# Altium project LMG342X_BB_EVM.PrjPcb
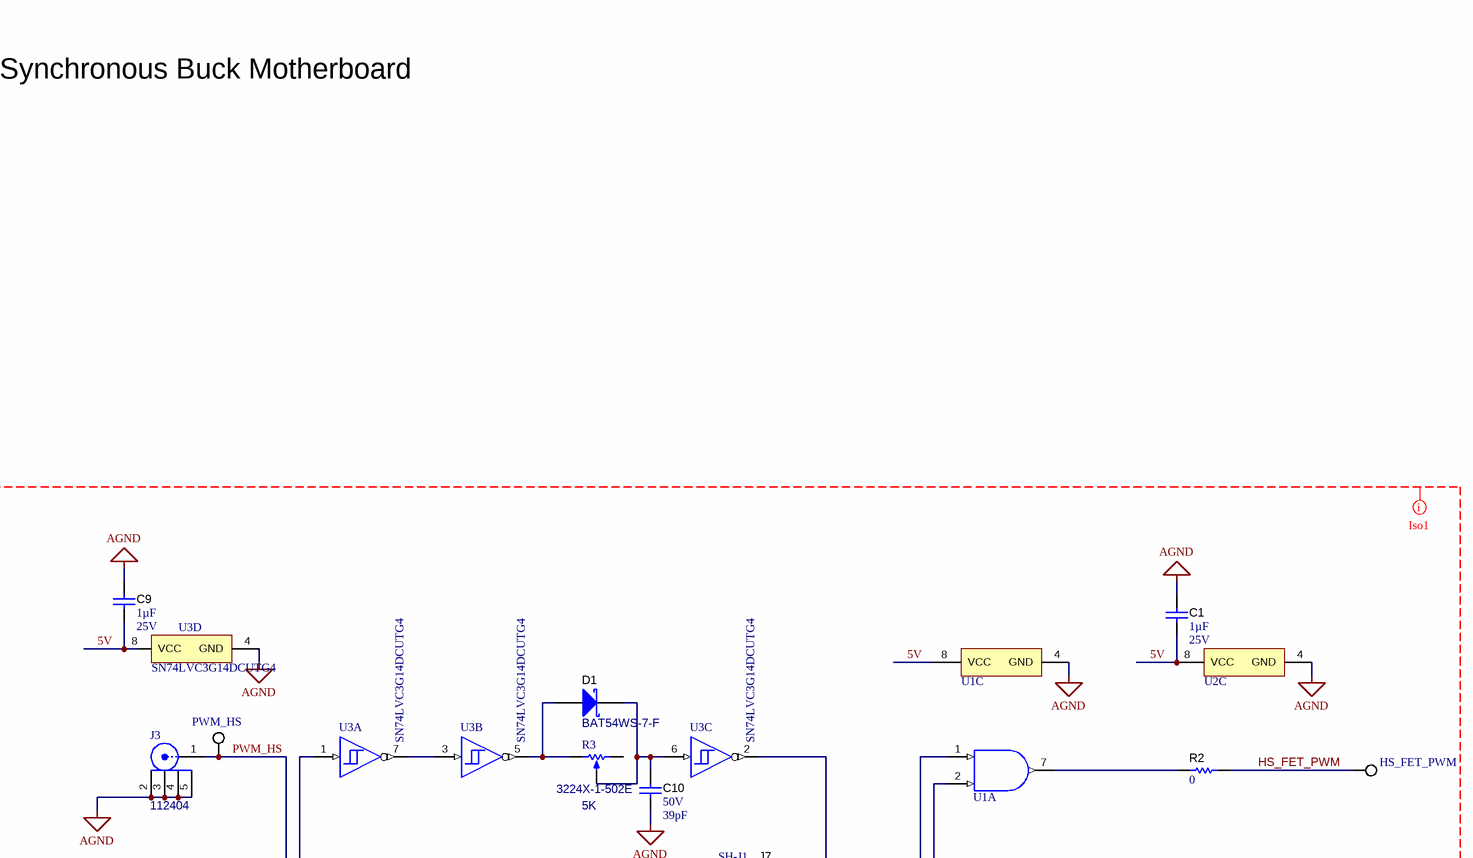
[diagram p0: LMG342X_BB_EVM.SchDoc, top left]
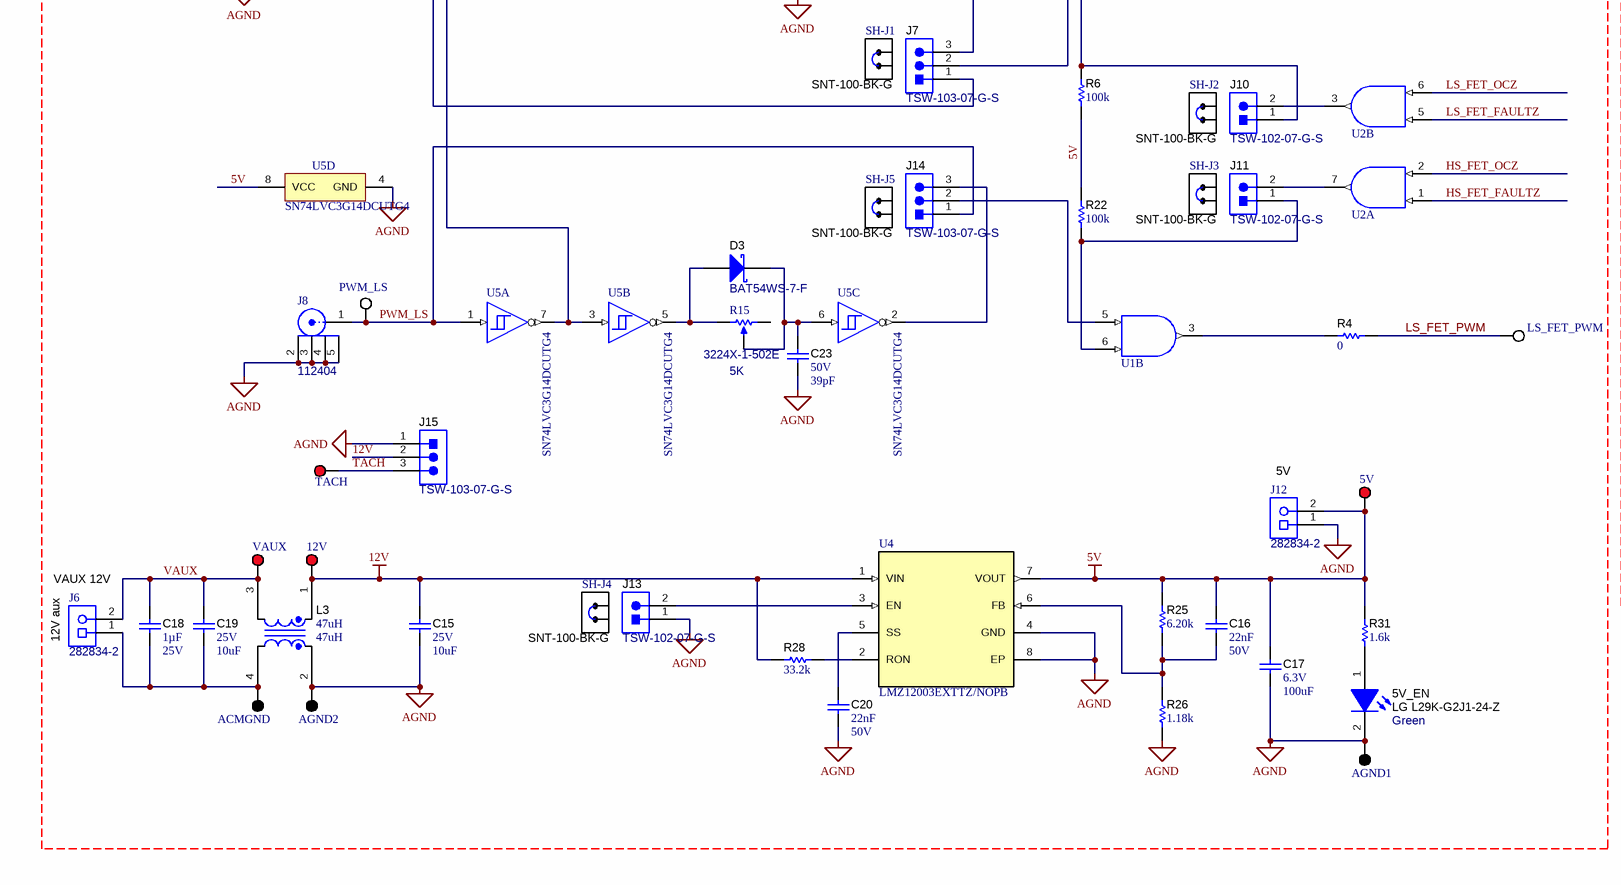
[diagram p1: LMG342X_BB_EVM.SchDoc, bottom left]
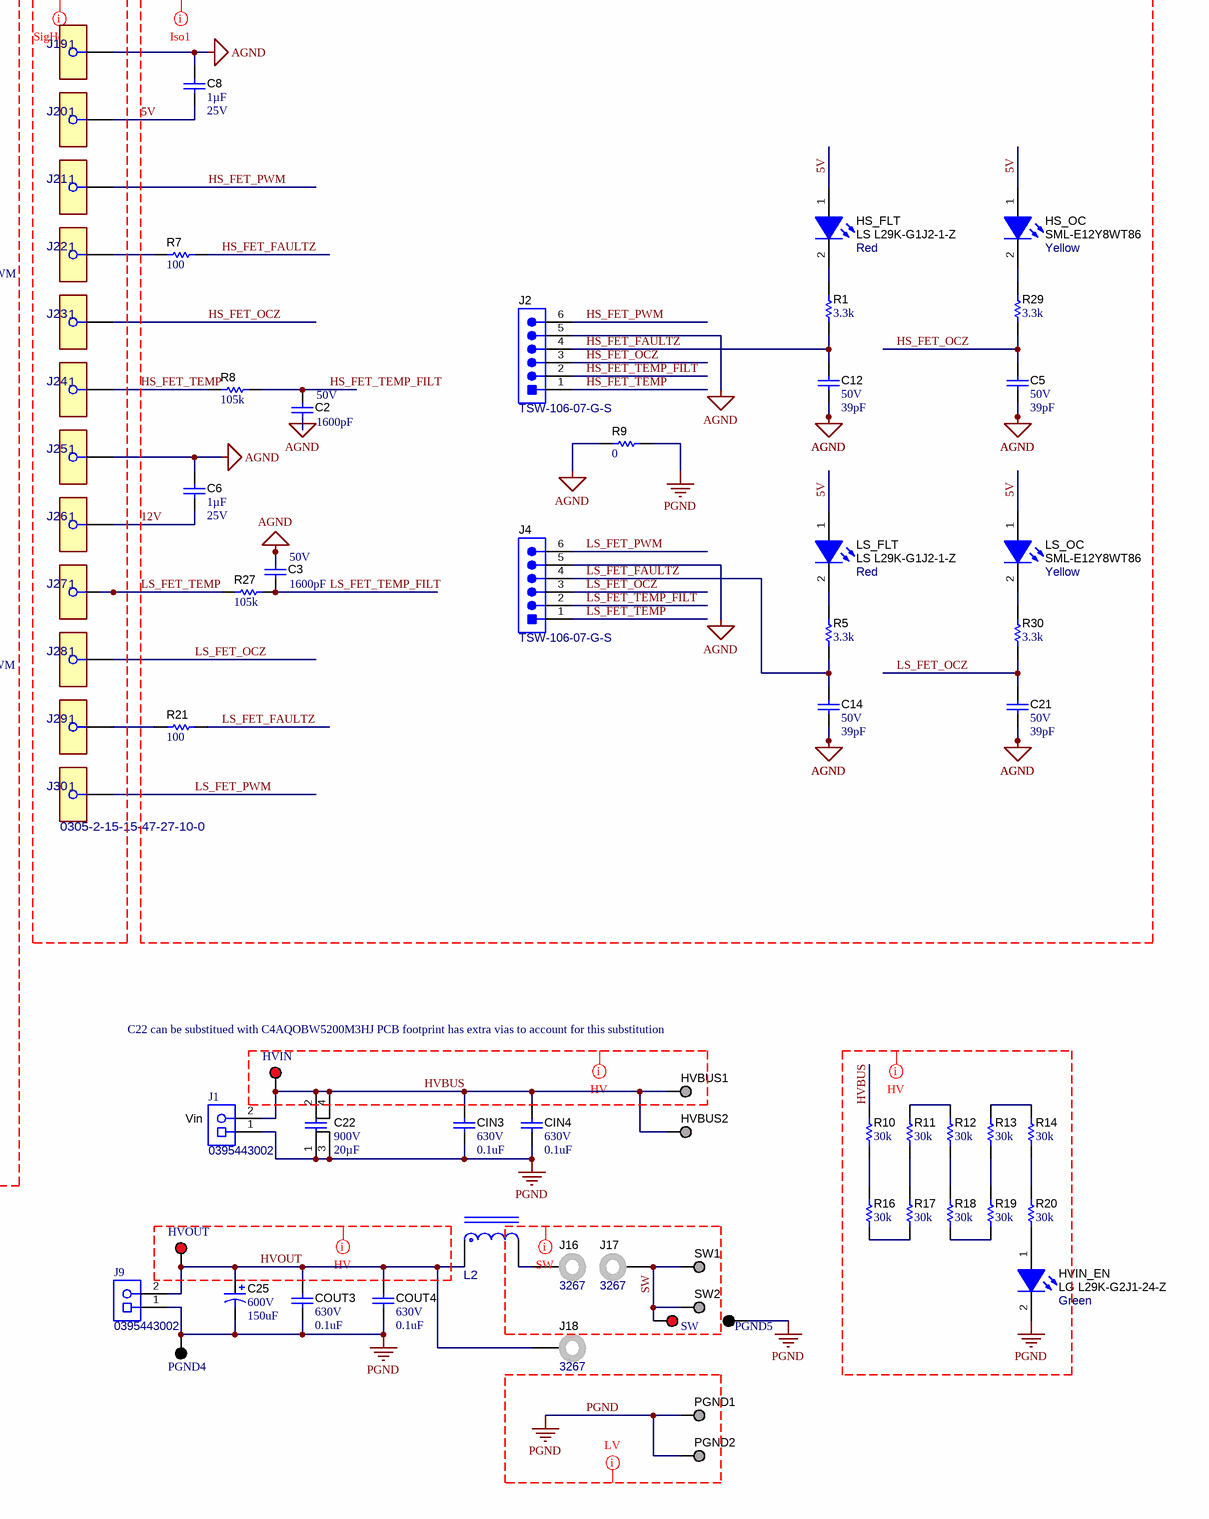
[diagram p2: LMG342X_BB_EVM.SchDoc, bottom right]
CopyrightYear: 2020; PCB_Layout: Kyle Wolf; PCB_Rev: A1; PRJ_Customer: General Release; PRJ_Engineer: Kyle Wolf; PRJ_Number: HVP049; PRJ_Title: LMG342X-BB-EVM; SCH_Rev: A1; TechSupport: http://www.ti.com/support; TID: N/A
2 sheets, 158 parts. Net scope: global (net labels, ports and power ports of the same name join across sheets).
Board file: LMG342X_BB_EVM.PcbDoc
Sheets:
  LMG342X_BB_EVM.SchDoc
  LMG342X_BB_EVM_Hardware.SchDoc

## Sheet LMG342X_BB_EVM.SchDoc
size 558 x 431 mm; Date: Not shown in title block; ApprovedBy: Not shown in title block; CheckedBy: Not shown in title block; Author: Not shown in title block; CompanyName: Not shown in title block; Engineer: Not shown in title block; Organization: Not shown in title block; Address1: Not shown in title block; Address2: Not shown in title block; Address3: Not shown in title block; Address4: Not shown in title block; DocumentNumber: 1; Revision: Use project parameter SCH_Rev; SheetNumber: 2; SheetTotal: 3; PageSetup: Record=PageOptions¦CenterHorizontal=True¦CenterVertical=True¦PrintScale=1.00¦XCorrection=1.00¦YCorrection=1.00¦PrintKind=0¦BorderSize=5000000¦LeftOffset=0¦BottomOffset=0¦Orientation=2¦PaperLength=1000¦PaperWidth=1000¦Scale=100¦PaperSource=15¦PrintQuality=600¦MediaType=1¦DitherType=10¦PaperKind=Letter¦PrintScaleMode=1

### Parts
5V  5005  [Keystone5005]  (value not drawn)
5V_EN  LG L29K-G2J1-24-Z  value Green  [LG L29K_GREEN]
12V  5005  [Keystone5005]  (value not drawn)
ACMGND  5006  [Keystone5006]  (value not drawn)
AGND1  5006  [Keystone5006]  (value not drawn)
AGND2  5006  [Keystone5006]  (value not drawn)
C1  Cap_F: 1µF  VDC_V: 25V  [0603]  (hidden comment: CGA3E1X7R1E105K080AD)
C2  VDC_V: 50V  ValueDisplayed: 1600pF  [0603]  (hidden comment: GRM1885C1H162JA01D)
C3  VDC_V: 50V  ValueDisplayed: 1600pF  [0603]  (hidden comment: GRM1885C1H162JA01D)
C5  VDC_V: 50V  ValueDisplayed: 39pF  [0603]  (hidden comment: GRM1885C1H390JA01D)
C6  Cap_F: 1µF  VDC_V: 25V  [0603]  (hidden comment: CGA3E1X7R1E105K080AD)
C8  Cap_F: 1µF  VDC_V: 25V  [0603]  (hidden comment: CGA3E1X7R1E105K080AD)
C9  Cap_F: 1µF  VDC_V: 25V  [0603]  (hidden comment: CGA3E1X7R1E105K080AD)
C10  VDC_V: 50V  ValueDisplayed: 39pF  [0603]  (hidden comment: GRM1885C1H390JA01D)
C12  VDC_V: 50V  ValueDisplayed: 39pF  [0603]  (hidden comment: GRM1885C1H390JA01D)
C14  VDC_V: 50V  ValueDisplayed: 39pF  [0603]  (hidden comment: GRM1885C1H390JA01D)
C15  VDC_V: 25V  ValueDisplayed: 10uF  [0603]  (hidden comment: GRT188R61E106ME13D)
C16  Cap_F: 22nF  VDC_V: 50V  [0603]  (hidden comment: 885012206091)
C17  VDC_V: 6.3V  ValueDisplayed: 100uF  [0805_HV]  (hidden comment: GRM21BR60J107M)
C18  Cap_F: 1µF  VDC_V: 25V  [0603]  (hidden comment: CGA3E1X7R1E105K080AD)
C19  VDC_V: 25V  ValueDisplayed: 10uF  [0805_HV]  (hidden comment: CL21A106KAFN3NE)
C20  Cap_F: 22nF  VDC_V: 50V  [0603]  (hidden comment: 885012206091)
C21  VDC_V: 50V  ValueDisplayed: 39pF  [0603]  (hidden comment: GRM1885C1H390JA01D)
C22  VDC_V: 900V  ValueDisplayed: 20µF  [FE37M]  (hidden comment: FE37M6C0206KB)
C23  VDC_V: 50V  ValueDisplayed: 39pF  [0603]  (hidden comment: GRM1885C1H390JA01D)
C25  VDC_V: 600V  ValueDisplayed: 150uF  [Nichicon_3000x5000_Snap]  (hidden comment: LGN2X151MELB50)
CIN3  VDC_V: 630V  ValueDisplayed: 0.1uF  [1812_HV]  (hidden comment: GRM43DR72J104KW01L)
CIN4  VDC_V: 630V  ValueDisplayed: 0.1uF  [1812]  (hidden comment: GRM43DR72J104KW01L)
COUT3  VDC_V: 630V  ValueDisplayed: 0.1uF  [1812_HV]  (hidden comment: GRM43DR72J104KW01L)
COUT4  VDC_V: 630V  ValueDisplayed: 0.1uF  [1812_HV]  (hidden comment: GRM43DR72J104KW01L)
D1  BAT54WS-7-F  [SOD-323]
D3  BAT54WS-7-F  [SOD-323]
HS_FET_PWM  5007  [Keystone5007]  (value not drawn)
HS_FLT  LS L29K-G1J2-1-Z  value Red  [LS L29K_Red]
HS_OC  SML-E12Y8WT86  value Yellow  [SML-E1_Yellow]
HVBUS1  0312-0-15-15-34-27-10-0  [Mill-Max_0312-0-15-15-34-27-10-0]  (value not drawn)
HVBUS2  0312-0-15-15-34-27-10-0  [Mill-Max_0312-0-15-15-34-27-10-0]  (value not drawn)
HVIN  5005  [Keystone5005]  (value not drawn)
HVIN_EN  LG L29K-G2J1-24-Z  value Green  [LG L29K_GREEN]
HVOUT  5005  [Keystone5005]  (value not drawn)
J1  0395443002  [Molex_0395443002]
J2  TSW-106-07-G-S  [TSW-106-07-G-S]
J3  112404  [Amphenol_112404]
J4  TSW-106-07-G-S  [TSW-106-07-G-S]
J6  282834-2  [TEC_282834-2]
J7  TSW-103-07-G-S  [TSW-103-07-G-S]
J8  112404  [Amphenol_112404]
J9  0395443002  [Molex_0395443002]
J10  TSW-102-07-G-S  [TSW-102-07-G-S]
J11  TSW-102-07-G-S  [TSW-102-07-G-S]
J12  282834-2  [TEC_282834-2]
J13  TSW-102-07-G-S  [TSW-102-07-G-S]
J14  TSW-103-07-G-S  [TSW-103-07-G-S]
J15  TSW-103-07-G-S  [TSW-103-07-G-S]
J16  3267  [Pomona_3267]
J17  3267  [Pomona_3267]
J18  3267  [Pomona_3267]
J19  0305-2-15-15-47-27-10-0  [FP-0305-2-15-15-47-27-10-0_CONN_PIN_RCPT-MFG]  (value not drawn)
J20  0305-2-15-15-47-27-10-0  [FP-0305-2-15-15-47-27-10-0_CONN_PIN_RCPT-MFG]  (value not drawn)
J21  0305-2-15-15-47-27-10-0  [FP-0305-2-15-15-47-27-10-0_CONN_PIN_RCPT-MFG]  (value not drawn)
J22  0305-2-15-15-47-27-10-0  [FP-0305-2-15-15-47-27-10-0_CONN_PIN_RCPT-MFG]  (value not drawn)
J23  0305-2-15-15-47-27-10-0  [FP-0305-2-15-15-47-27-10-0_CONN_PIN_RCPT-MFG]  (value not drawn)
J24  0305-2-15-15-47-27-10-0  [FP-0305-2-15-15-47-27-10-0_CONN_PIN_RCPT-MFG]  (value not drawn)
J25  0305-2-15-15-47-27-10-0  [FP-0305-2-15-15-47-27-10-0_CONN_PIN_RCPT-MFG]  (value not drawn)
J26  0305-2-15-15-47-27-10-0  [FP-0305-2-15-15-47-27-10-0_CONN_PIN_RCPT-MFG]  (value not drawn)
J27  0305-2-15-15-47-27-10-0  [FP-0305-2-15-15-47-27-10-0_CONN_PIN_RCPT-MFG]  (value not drawn)
J28  0305-2-15-15-47-27-10-0  [FP-0305-2-15-15-47-27-10-0_CONN_PIN_RCPT-MFG]  (value not drawn)
J29  0305-2-15-15-47-27-10-0  [FP-0305-2-15-15-47-27-10-0_CONN_PIN_RCPT-MFG]  (value not drawn)
J30  0305-2-15-15-47-27-10-0  [FP-0305-2-15-15-47-27-10-0_CONN_PIN_RCPT-MFG]
L2  750317345  [FP-750317345_PTH_D53MM34-MFG]  (value not drawn)
L3  value 47uH  [DRQ73]  (hidden comment: DRQ73-470-R)
LS_FET_PWM  5007  [Keystone5007]  (value not drawn)
LS_FLT  LS L29K-G1J2-1-Z  value Red  [LS L29K_Red]
LS_OC  SML-E12Y8WT86  value Yellow  [SML-E1_Yellow]
PGND1  0312-0-15-15-34-27-10-0  [Mill-Max_0312-0-15-15-34-27-10-0]  (value not drawn)
PGND2  0312-0-15-15-34-27-10-0  [Mill-Max_0312-0-15-15-34-27-10-0]  (value not drawn)
PGND4  5006  [Keystone5006]  (value not drawn)
PGND5  5006  [Keystone5006]  (value not drawn)
PWM_HS  5007  [Keystone5007]  (value not drawn)
PWM_LS  5007  [Keystone5007]  (value not drawn)
R1  ValueDisplayed: 3.3k  [0603]  (hidden comment: CRCW06033K30JNEA)
R2  ValueDisplayed: 0  [0603_HV]  (hidden comment: CRCW06030000Z0EA)
R3  3224X-1-502E  value 5K  [TRIM_3224X]
R4  ValueDisplayed: 0  [0603_HV]  (hidden comment: CRCW06030000Z0EA)
R5  ValueDisplayed: 3.3k  [0603]  (hidden comment: CRCW06033K30JNEA)
R6  ValueDisplayed: 100k  [0603]  (hidden comment: CRCW0603100KJNEAC)
R7  ValueDisplayed: 100  [0603]  (hidden comment: CRCW0603100RJNEA)
R8  ValueDisplayed: 105k  [0603]  (hidden comment: RC0603FR-07105KL)
R9  ValueDisplayed: 0  [0603_HV]  (hidden comment: CRCW06030000Z0EA)
R10  ValueDisplayed: 30k  [1206]  (hidden comment: CRCW120630K0JNEA)
R11  ValueDisplayed: 30k  [1206]  (hidden comment: CRCW120630K0JNEA)
R12  ValueDisplayed: 30k  [1206]  (hidden comment: CRCW120630K0JNEA)
R13  ValueDisplayed: 30k  [1206]  (hidden comment: CRCW120630K0JNEA)
R14  ValueDisplayed: 30k  [1206]  (hidden comment: CRCW120630K0JNEA)
R15  3224X-1-502E  value 5K  [TRIM_3224X]
R16  ValueDisplayed: 30k  [1206]  (hidden comment: CRCW120630K0JNEA)
R17  ValueDisplayed: 30k  [1206]  (hidden comment: CRCW120630K0JNEA)
R18  ValueDisplayed: 30k  [1206]  (hidden comment: CRCW120630K0JNEA)
R19  ValueDisplayed: 30k  [1206]  (hidden comment: CRCW120630K0JNEA)
R20  ValueDisplayed: 30k  [1206]  (hidden comment: CRCW120630K0JNEA)
R21  ValueDisplayed: 100  [0603]  (hidden comment: CRCW0603100RJNEA)
R22  ValueDisplayed: 100k  [0603]  (hidden comment: CRCW0603100KJNEAC)
R25  ValueDisplayed: 6.20k  [0603]  (hidden comment: RC0603FR-076K2L)
R26  ValueDisplayed: 1.18k  [0603]  (hidden comment: RC0603FR-071K18L)
R27  ValueDisplayed: 105k  [0603]  (hidden comment: RC0603FR-07105KL)
R28  ValueDisplayed: 33.2k  [0603]  (hidden comment: RT0603BRD0733K2L)
R29  ValueDisplayed: 3.3k  [0603]  (hidden comment: CRCW06033K30JNEA)
R30  ValueDisplayed: 3.3k  [0603]  (hidden comment: CRCW06033K30JNEA)
R31  ValueDisplayed: 1.6k  [0603]  (hidden comment: CRCW06031K60JNEA)
SH-J1  SNT-100-BK-G  [SNT-100-BK-G]
SH-J2  SNT-100-BK-G  [SNT-100-BK-G]
SH-J3  SNT-100-BK-G  [SNT-100-BK-G]
SH-J4  SNT-100-BK-G  [SNT-100-BK-G]
SH-J5  SNT-100-BK-G  [SNT-100-BK-G]
SW  5005  [Keystone5005]  (value not drawn)
SW1  0312-0-15-15-34-27-10-0  [Mill-Max_0312-0-15-15-34-27-10-0]  (value not drawn)
SW2  0312-0-15-15-34-27-10-0  [Mill-Max_0312-0-15-15-34-27-10-0]  (value not drawn)
TACH  5005  [Keystone5005]  (value not drawn)
U1  SN74LVC2G08IDCTRQ1  [DCT0008A_N]  (value not drawn)  (parts A,B,C of 3)
U2  SN74LVC2G08IDCTRQ1  [DCT0008A_N]  (value not drawn)  (parts A,B,C of 3)
U3  SN74LVC3G14DCUTG4  [DCU0008A_N]  (parts A,B,C,D of 4)
U4  LMZ12003EXTTZ/NOPB  [NDW0007A_V]
U5  SN74LVC3G14DCUTG4  [DCU0008A_N]  (parts A,B,C,D of 4)
VAUX  5005  [Keystone5005]  (value not drawn)

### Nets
5V: 5V.1 C1.2 C8.1 C9.2 C16.1 C17.1 HS_FLT.1(A) HS_OC.1(A) J12.2 J20.1 LS_FLT.1(A) LS_OC.1(A) R6.1 R22.2 R25.2 R31.2 U1.8(VCC) U2.8(VCC) U3.8(VCC) U4.7(VOUT) U5.8(VCC)
12V: 12V.1 C6.1 C15.1 J15.2 J26.1 L3.1 R28.1 U4.1(VIN)
AGND: 5V_EN.2(K) AGND1.1 AGND2.1 C1.1 C2.1 C3.1 C5.2 C6.2 C8.2 C9.1 C10.2 C12.2 C14.2 C15.2 C17.2 C20.2 C21.2 C23.2 J2.5 J3.2 J3.3 J3.4 J3.5 J4.5 J8.2 J8.3 J8.4 J8.5 J12.1 J13.1 J15.1 J19.1 J25.1 L3.2 R9.1 R26.1 U1.4(GND) U2.4(GND) U3.4(GND) U4.4(GND) U4.8(EP) U5.4(GND)
PGND: C22.1 C22.3 C25.2(-) CIN3.2 CIN4.2 COUT3.2 COUT4.2 HVIN_EN.2(K) J1.1 J9.1 PGND1.1 PGND2.1 PGND4.1 PGND5.1 R9.2
HS_FET_FAULTZ: C12.1 J2.4 R1.1 R7.2 U2.1(1A)
HS_FET_OCZ: C5.1 J2.3 J23.1 R29.1 U2.2(1B)
HS_FET_PWM: HS_FET_PWM.1 J2.6 J21.1 R2.2
HS_FET_TEMP: J2.1 J24.1 R8.1
HS_FET_TEMP_FILT: C2.2 J2.2 R8.2
HVBUS: C22.2 C22.4 CIN3.1 CIN4.1 HVBUS1.1 HVBUS2.1 HVIN.1 J1.2 R10.2
HVOUT: C25.1(+) COUT3.1 COUT4.1 HVOUT.1 J9.2 J18.1 L2.1(S)
LS_FET_FAULTZ: C14.1 J4.4 R5.1 R21.2 U2.5(2A)
LS_FET_OCZ: C21.1 J4.3 J28.1 R30.1 U2.6(2B)
LS_FET_PWM: J4.6 J30.1 LS_FET_PWM.1 R4.2
LS_FET_TEMP: J4.1 J27.1 R27.1
LS_FET_TEMP_FILT: C3.2 J4.2 R27.2
PWM_HS: J3.1 J7.1 PWM_HS.1
PWM_LS: J8.1 J14.1 PWM_LS.1 U5.1(1A)
SW: J17.1 SW.1 SW1.1 SW2.1
TACH: J15.3 TACH.1
VAUX: C18.1 C19.1 J6.2 L3.3 VAUX.1
Net5V_EN_1: 5V_EN.1(A) R31.1
NetACMGND_1: ACMGND.1 C18.2 C19.2 J6.1 L3.4
NetC10_1: C10.1 D1.1(K) R3.2(WIPER) U3.6(3A)
NetC16_2: C16.2 R25.1 R26.2 U4.6(FB)
NetC20_1: C20.1 U4.5(SS)
NetC23_1: C23.1 D3.1(K) R15.2(WIPER) U5.6(3A)
NetD1_2: D1.2(A) R3.1(CCW) U3.5(2Y)
NetD3_2: D3.2(A) R15.1(CCW) U5.5(2Y)
NetHS_FLT_2: HS_FLT.2(K) R1.2
NetHS_OC_2: HS_OC.2(K) R29.2
NetHVIN_EN_1: HVIN_EN.1(A) R20.1
NetJ7_2: J7.2 U1.1(1A)
NetJ7_3: J7.3 U3.2(3Y)
NetJ10_1: J10.1 R6.2 U1.2(1B)
NetJ10_2: J10.2 U2.3(2Y)
NetJ11_1: J11.1 R22.1 U1.6(2B)
NetJ11_2: J11.2 U2.7(1Y)
NetJ13_2: J13.2 U4.3(EN)
NetJ14_2: J14.2 U1.5(2A)
NetJ14_3: J14.3 U5.2(3Y)
NetJ16_1: J16.1 L2.2(F)
NetJ22_1: J22.1 R7.1
NetJ29_1: J29.1 R21.1
NetLS_FLT_2: LS_FLT.2(K) R5.2
NetLS_OC_2: LS_OC.2(K) R30.2
NetR2_1: R2.1 U1.7(1Y)
NetR4_1: R4.1 U1.3(2Y)
NetR10_1: R10.1 R16.2
NetR11_1: R11.1 R17.2
NetR11_2: R11.2 R12.2
NetR12_1: R12.1 R18.2
NetR13_1: R13.1 R19.2
NetR13_2: R13.2 R14.2
NetR14_1: R14.1 R20.2
NetR16_1: R16.1 R17.1
NetR18_1: R18.1 R19.1
NetR28_2: R28.2 U4.2(RON)
NetU3_1: U3.1(1A) U5.3(2A) U5.7(1Y)
NetU3_3: U3.3(2A) U3.7(1Y)

Not connected (* = marked no-connect by the designer): R3 3(CW); R15 3(CW)

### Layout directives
net class HV: HVBUS, HVOUT, PGND
net class SW: SW
net class LV: PGND
net class Iso1: 5V, 12V, AGND, HS_FET_FAULTZ, HS_FET_OCZ, HS_FET_PWM, HS_FET_TEMP, HS_FET_TEMP_FILT, LS_FET_FAULTZ, LS_FET_OCZ, LS_FET_PWM, LS_FET_TEMP, LS_FET_TEMP_FILT, PGND, PWM_HS, PWM_LS, TACH, VAUX
net class SigHeader: (no net found under the mark)

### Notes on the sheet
- TI HV Synchronous Buck Motherboard
- (near J12) 5V
- (near J6) 12V aux
- (near J6) VAUX 12V
- C22 can be substitued with C4AQOBW5200M3HJ PCB footprint has extra vias to account for this substitution
- (near J1) Vin

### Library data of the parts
5V 12V HVIN HVOUT SW TACH VAUX = CMP-0055142-1: Test Point, Compact, Red, TH; Manufacturer: Keystone; CNHeader: FALSE; Green_Lifecycle: Active; Green_REACh: Passed; ContactFinish: Silver; CT: TRUE
5V_EN HVIN_EN = CMP-0002874-2: LED, Green, SMD; Manufacturer: OSRAM; Io_A: 2mA; Value2: 1.7V; Value1: W; Tjmax_C: 110°C
ACMGND AGND1 AGND2 PGND4 PGND5 = CMP-0055143-1: Test Point, Compact, Black, TH; Manufacturer: Keystone; CNHeader: FALSE; Green_Lifecycle: Active; Green_REACh: Passed; ContactFinish: Silver; CT: TRUE
C1 C6 C8 C9 C18 = CMP-0082523-1: CAP, CERM, 1 µF, 25 V,+/- 10%, X7R, AEC-Q200 Grade 1, 0603; Manufacturer: TDK; SizeAreaWB_mm2: 4.68; SizeArea_mm2: 1.28; AEC Qualified: Y; AEC Category: Q200; Value: 1uF; TaMax_C: 125°C; SizeZ_mm: 1; Polarized: N; TaMin_C: -55°C; SizeY_mm: 0.8; U/M: EA; SizeX_mm: 1.6
C2 C3 = CMP-0007189-1: CAP, CERM, 1600 pF, 50 V, +/- 5%, C0G/NP0, 0603; Manufacturer: MuRata; TaMin_C: -55°C; Polarized: N; SizeAreaWB_mm2: 4.68; Value1: Unknown; U/M: EA; Value: 1600pF; TaMax_C: 125°C; SizeZ_mm: 1; SizeX_mm: 1.6; SizeY_mm: 0.8; SizeArea_mm2: 1.28; Cap_F: 1.6nF; AEC Category: Q200
C5 C10 C12 C14 C21 C23 = CMP-0007214-4: CAP, CERM, 39 pF, 50 V, +/- 5%, C0G/NP0, 0603; Manufacturer: MuRata; TaMin_C: -55°C; Polarized: N; SizeAreaWB_mm2: 4.68; Value1: Unknown; U/M: EA; Value: 39pF; TaMax_C: 125°C; SizeZ_mm: 1; SizeX_mm: 1.6; SizeY_mm: 0.8; SizeArea_mm2: 1.28; AEC Category: Q200
C15 = CMP-0007501-1: CAP, CERM, 10 uF, 25 V, +/- 20%, X5R, 0603; Manufacturer: MuRata; TaMin_C: -55°C; Polarized: N; SizeAreaWB_mm2: 4.68; Value1: Unknown; U/M: EA; Value: 10uF; TaMax_C: 85°C; SizeZ_mm: 1; SizeX_mm: 1.6; SizeY_mm: 0.8; SizeArea_mm2: 1.28; Cap_F: 10µF; AEC Category: Q200
C16 C20 = CMP-0006836-1: CAP, CERM, 0.022 uF, 50 V, +/- 10%, X7R, 0603; Manufacturer: Wurth Elektronik; TaMin_C: -55°C; Polarized: N; SizeAreaWB_mm2: 4.68; Value1: Unknown; U/M: EA; TaMax_C: 125°C; SizeZ_mm: 1; SizeX_mm: 1.6; SizeY_mm: 0.8; SizeArea_mm2: 1.28; AEC Category: Q200
C17 = CMP-0008280-1: CAP, CERM, 100 uF, 6.3 V, +/- 20%, X5R, 0805; Manufacturer: MuRata; TaMin_C: -55°C; Polarized: N; SizeAreaWB_mm2: 6.75; Value1: Unknown; U/M: EA; Value: 100uF; TaMax_C: 85°C; SizeZ_mm: 1.45; SizeX_mm: 2; SizeY_mm: 1.25; Cap_Case: 0805; SizeArea_mm2: 2.5; Cap_F: 100µF; AEC Category: Q200
C19 = CMP-0007987-2: CAP, CERM, 10 uF, 25 V, +/- 10%, X5R, 0805; Manufacturer: Samsung Electro-Mechanics; TaMin_C: -55°C; Polarized: N; SizeAreaWB_mm2: 6.75; Value1: Unknown; U/M: EA; Value: 10uF; TaMax_C: 85°C; SizeZ_mm: 1.45; SizeX_mm: 2; SizeY_mm: 1.25; Cap_Case: 0805; SizeArea_mm2: 2.5; Cap_F: 10µF; AEC Category: Q200
C22 = CMP-0083986-1: CAP, Film, 20 µF, 900 V,+/- 10%, 0.0055 ohm, TH; Manufacturer: AVX; IRMS_A: 15A; SizeAreaWB_mm2: 1424; SizeArea_mm2: 1275; AEC Qualified: N; AEC Category: Q200; Value: 20uF; TaMax_C: 100°C; SizeZ_mm: 45.5; TaMin_C: -40°C; SizeY_mm: 30; CompType: Capacitor; SizeX_mm: 42.5; ESR_ohm: 5.5m; Cap_Case: 42.5x30x45mm
C25 = CMP-0010059-2: CAP, AL, 150 uF, 600 V, +/- 20%, TH; Manufacturer: Nichicon; TaMin_C: -25°C; Polarized: Y; SizeAreaWB_mm2: 1024; Value1: Unknown; U/M: EA; Value: 150uF; TaMax_C: 105°C; SizeZ_mm: 52; SizeX_mm: 30; Cap_Case: 30x50mm; SizeArea_mm2: 900; CompType: Capacitor; AEC Qualified: N; Cap_F: 150µF; IRMS_A: 830mA; AEC Category: Q200
CIN3 COUT3 COUT4 = CMP-0009455-2: CAP, CERM, 0.1 uF, 630 V, +/- 10%, X7R, 1812; Manufacturer: MuRata; TaMin_C: -55°C; Polarized: N; SizeAreaWB_mm2: 23.1; Value1: Unknown; U/M: EA; Value: 0.1uF; TaMax_C: 125°C; SizeZ_mm: 1.35; SizeX_mm: 4.5; SizeY_mm: 3.2; Cap_Case: 1812; SizeArea_mm2: 14.4; Cap_F: 100nF; AEC Category: Q200
CIN4 = CMP-0009455-2: CAP, CERM, 0.1 uF, 630 V, +/- 10%, X7R, 1812; Manufacturer: MuRata; TaMin_C: -55°C; Polarized: N; SizeAreaWB_mm2: 23.1; Value1: Unknown; U/M: EA; Value: 0.1uF; TaMax_C: 125°C; SizeZ_mm: 1.35; SizeX_mm: 4.5; SizeY_mm: 3.2; SizeArea_mm2: 14.4; Cap_F: 100nF; AEC Category: Q200
D1 D3 = CMP-0028458-1: Diode, Schottky, 30 V, 0.2 A, SOD-323; Manufacturer: Diodes Inc.; Io_A: 200mA; Green_Lifecycle: Active; SizeAreaWB_mm2: 8.695; Vr_V: 30V; Green_REACh: Passed; Value1: 0.2A; TJmax_C: 125°C; U/M: EA; Value: 30V; SizeZ_mm: 1; SizeX_mm: 2.7; SizeY_mm: 1.35; Vf_V: 700mV; Value2: 0.7V; SizeArea_mm2: 3.645; AEC Category: Q101
HS_FET_PWM LS_FET_PWM PWM_HS PWM_LS = CMP-0055144-1: Test Point, Compact, White, TH; Manufacturer: Keystone; CNHeader: FALSE; Green_Lifecycle: Active; Green_REACh: Passed; ContactFinish: Silver; CT: TRUE
HS_FLT LS_FLT = CMP-0002902-2: LED, Red, SMD; Manufacturer: OSRAM; Io_A: 20mA; Vr_V: 12V; Tjmax_C: 110°C; Value1: W; Angle: 160; Vf_V: 1.8V
HS_OC LS_OC = CMP-0002977-1: LED, Yellow, SMD; Manufacturer: Rohm; Io_A: 20mA; Power_TotalModule: 54mW; Vr_V: 5V; Tjmax_C: 85°C; Value1: 0.054W; U/M: EA; Ir_A: 10µA; Vf_V: 2.2V; LuminousIntensity_IV: 63
HVBUS1 HVBUS2 PGND1 PGND2 SW1 SW2 = CMP-0055026-1: Manufacturer: Mill-Max; CNHeader: FALSE; Green_Lifecycle: Active; Gender: Female; Green_REACh: Passed; CompType: Pin Receptacle; ContactFinish: Gold
J1 J9 = CMP-0055342-2: Terminal Block, 5.08mm, 2x1, TH; Manufacturer: Molex; Current_A: 15A; Green_Lifecycle: Not Set; Gender: Female; Green_REACh: Incomplete; Voltage_V: 300V; Row_Count: 1; Pitch_mm: 5.08
J2 J4 = CMP-0075413-2: Header, 100mil, 6x1, Gold, TH; Manufacturer: Samtec; Pitch_mm: 2.54; Cert_VDE: N; Gender: Male; Cert_CSA: Y; Voltage_V: 550V; Green_REACh: Passed; Current_A: 6.3A; Green_Lifecycle: Active; Row_Count: 1
J3 J8 = CMP-0055424-1: Connector, TH, BNC; Manufacturer: Amphenol Connex; CT: TRUE; Green_REACh: Incomplete; CNHeader: FALSE; Green_Lifecycle: Not Set
J6 J12 = CMP-0054974-1: Terminal Block, 2x1, 2.54mm, TH; Manufacturer: TE Connectivity; CNHeader: FALSE; Green_Lifecycle: Active; Green_REACh: Passed; CT: TRUE
J7 J14 J15 = CMP-0075407-2: Header, 100mil, 3x1, Gold, TH; Manufacturer: Samtec; Pitch_mm: 2.54; Cert_VDE: N; Gender: Male; Cert_CSA: Y; Voltage_V: 550V; Green_REACh: Passed; Current_A: 6.3A; Green_Lifecycle: Active; Row_Count: 1
J10 J11 J13 = CMP-0075405-2: Header, 100mil, 2x1, Gold, TH; Manufacturer: Samtec; Pitch_mm: 2.54; Cert_VDE: N; Gender: Male; Cert_CSA: Y; Voltage_V: 550V; Green_REACh: Passed; Current_A: 6.3A; Green_Lifecycle: Active; Row_Count: 1
J16-J18 = CMP-0055388-2: Standard Banana Jack, Uninsulated; Manufacturer: Pomona Electronics; CT: TRUE; Green_REACh: Incomplete; CNHeader: FALSE; Green_Lifecycle: Not Set
J19-J30 = CMP-0120348-1: Pin Receptacle Connector 0.025" ~ 0.037" (0.64mm ~ 0.94mm) No Tail Solder; Manufacturer: Mill-Max; ContactFinish: Gold,Nickel; Current_A: 4.5A; Conn Gender: Female; Conn Orientation: Straight; Is Female: yes
L2 = CMP-0090191-1: INDUCTOR 570uH 13A; Manufacturer: Wurth Electronics; DCR_ohm: 0.063; SizeZ_mm: 25.4mm; Ind_H: 570µH; AEC Qualified: No; Tolerance_%: 10%; Test Frequency: 100kHz
L3 = CMP-0012771-2: Coupled inductor, 47 uH, 1.14 A, 0.4825 ohm, SMD; Manufacturer: Coiltronics; SizeAreaWB_mm2: 92.16; DCR_ohm: 0.4825; SizeZ_mm: 3.55; SizeX_mm: 7.6; SizeArea_mm2: 57.76; Ind_H: 47µH
R1 R5 R29 R30 = CMP-0025797-4: RES, 3.3 k, 5%, 0.1 W, AEC-Q200 Grade 0, 0603; Manufacturer: Vishay-Dale; Power_W: 100mW; TempCo: 200 ppm/C; Value_Code: 3k30; Value: 3.3k; EIA_Code: E24; SizeX_mm: 1.6; SizeY_mm: 0.8; SizeZ_mm: 1; Value2: 0.1W; SizeArea_mm2: 1.28; AEC Qualified: Y; VDC_V: 75V; AEC Category: Q200; AEC Grade: 0
R2 R4 R9 = CMP-0025697-4: RES, 0, 5%, 0.1 W, AEC-Q200 Grade 0, 0603; Manufacturer: Vishay-Dale; Power_W: 100mW; TempCo: 200 ppm/C; Value_Code: 0000; Value: 0; EIA_Code: E24; SizeX_mm: 1.6; SizeY_mm: 0.8; SizeZ_mm: 1; Value2: 0.1W; SizeArea_mm2: 1.28; AEC Qualified: Y; VDC_V: 75V; AEC Category: Q200
R3 R15 = CMP-0002062-2: Trimmer, 5 K, 0.25 W, SMD; Manufacturer: Bourns
R6 R22 = CMP-0082530-1: RES, 100 k, 5%, 0.1 W, 0603; Manufacturer: Vishay-Dale; Power_W: 100mW; TempCo: 200 ppm/C; SizeAreaWB_mm2: 4.68; Value: 100k; EIA_Code: E24; SizeX_mm: 1.6; SizeY_mm: 0.8; SizeZ_mm: 1; Value2: 0.1W; SizeArea_mm2: 1.28; AEC Qualified: N; VDC_V: 75V; AEC Category: Q200
R7 R21 = CMP-0025700-4: RES, 100, 5%, 0.1 W, AEC-Q200 Grade 0, 0603; Manufacturer: Vishay-Dale; Power_W: 100mW; TempCo: 200 ppm/C; Value_Code: 100R; Value: 100; EIA_Code: E24; SizeX_mm: 1.6; SizeY_mm: 0.8; SizeZ_mm: 1; Value2: 0.1W; SizeArea_mm2: 1.28; AEC Qualified: Y; VDC_V: 75V; AEC Category: Q200; AEC Grade: 0
R8 R27 = CMP-0022739-4: RES, 105 k, 1%, 0.1 W, 0603; Manufacturer: Yageo; Power_W: 100mW; TempCo: 100 ppm/C; Value: 105k; EIA_Code: E96; SizeX_mm: 1.6; SizeY_mm: 0.8; SizeZ_mm: 1; Value2: 0.1W; SizeArea_mm2: 1.28; AEC Qualified: N; VDC_V: 75V; AEC Category: Q200; SizeAreaWB_mm2: 4.68
R10-R14 R16-R20 = CMP-0018654-3: RES, 30 k, 5%, 0.25 W, AEC-Q200 Grade 0, 1206; Manufacturer: Vishay-Dale; Power_W: 250mW; TempCo: 200 ppm/C; Value_Code: 30k0; Value: 30k; EIA_Code: E24; SizeX_mm: 3.2; SizeY_mm: 1.6; SizeZ_mm: 1.35; Value2: 0.25W; SizeArea_mm2: 5.12; AEC Qualified: Y; VDC_V: 200V; AEC Category: Q200; AEC Grade: 0
R25 = CMP-0023248-5: RES, 6.20 k, 1%, 0.1 W, 0603; Manufacturer: Yageo; Power_W: 100mW; TempCo: 100 ppm/C; Value_Code: 6k20; Value: 6.20k; Res_ohm: 6.2k; SizeX_mm: 1.6; SizeY_mm: 0.8; SizeZ_mm: 1; Value2: 0.1W; SizeArea_mm2: 1.28; AEC Qualified: N; VDC_V: 75V; AEC Category: Q200; SizeAreaWB_mm2: 4.68
R26 = CMP-0022869-5: RES, 1.18 k, 1%, 0.1 W, 0603; Manufacturer: Yageo; Power_W: 100mW; TempCo: 100 ppm/C; Value_Code: 1k18; Value: 1.18k; EIA_Code: E96; SizeX_mm: 1.6; SizeY_mm: 0.8; SizeZ_mm: 1; Value2: 0.1W; SizeArea_mm2: 1.28; AEC Qualified: N; VDC_V: 75V; AEC Category: Q200; SizeAreaWB_mm2: 4.68
R28 = CMP-0024126-1: RES, 33.2 k, 0.1%, 0.1 W, 0603; Manufacturer: Yageo America; Power_W: 100mW; TempCo: 25 ppm/C; Value_Code: 33k2; U/M: EA; Value: 33.2k; EIA_Code: E192; SizeX_mm: 1.6; SizeY_mm: 0.8; SizeZ_mm: 1; Value2: 0.1W; SizeArea_mm2: 1.28; VDC_V: 75V; AEC Category: Q200
R31 = CMP-0025734-4: RES, 1.6 k, 5%, 0.1 W, AEC-Q200 Grade 0, 0603; Manufacturer: Vishay-Dale; Power_W: 100mW; TempCo: 200 ppm/C; Value_Code: 1k60; Value: 1.6k; EIA_Code: E24; SizeX_mm: 1.6; SizeY_mm: 0.8; SizeZ_mm: 1; Value2: 0.1W; SizeArea_mm2: 1.28; AEC Qualified: Y; VDC_V: 75V; AEC Category: Q200; AEC Grade: 0
SH-J1-SH-J5 = CMP-0003623-3: Shunt, 100mil, Gold plated, Black; Alternate PartNumber: 969102-0000-DA; Manufacturer: Samtec; Alternate Manufacturer: 3M; Value: 1x2
U1 U2 = CMP-0051803-1: Automotive Catalog Dual 2-Input Positive-AND Gate, DCT0008A, LARGE T&R; Manufacturer: Texas Instruments; Generic Part Number: SN74LVC2G08-Q1; F @ Nom Voltage(Max)(Mhz): 150; ICC @ Nom Voltage(Max)(mA): 0.01; Input Type: CMOS/TTL; Output Type: CMOS; Logic: True; VCC(Max)(V): 5.5; Technology Family: LVC; Schmitt Trigger: No; Bits(#): 2; tpd @ Nom Voltage(Max)(ns): 9,5.1,4.7,3.8; VCC(Min)(V): 1.65; Voltage(Nom)(V): 1.8,2.5,3.3,5; Output Drive (IOL/IOH)(Max)(mA): 32/-32
U3 U5 = CMP-0051969-2: Triple Schmitt-Trigger Inverter, DCU0008A (VSSOP-8); Manufacturer: Texas Instruments; Output Type: CMOS; Logic: Inverting; tpd @ Nom Voltage(Max)(ns): 9.2,5.7,5.4,4.3; Bits(#): 3; ICC @ Nom Voltage(Max)(mA): 0.01; Output Drive (IOL/IOH)(Max)(mA): 32/-32; F @ Nom Voltage(Max)(Mhz): 150; Voltage(Nom)(V): 1.8,2.5,3.3,5; Input Type: CMOS/TTL; Schmitt Trigger: Yes; VCC(Max)(V): 5.5; VCC(Min)(V): 1.65; Technology Family: LVC; Rating: Catalog; 3-State Output: No; AEC Category: Q200; AEC Qualified: N; CompType: IC; SizeAreaWB_mm2: 12.6; SizeArea_mm2: 6.4; SizeX_mm: 3.2; SizeY_mm: 2.0; SizeZ_mm: 0.9
U4 = CMP-0072360-1: 3A SIMPLE SWITCHER® Power Module with 20V Maximum Input Voltage for Military and Rugged Applications, 7 pin TO-PMOD; Manufacturer: Texas Instruments; PowerWise: Y; PackageTopMarking: NSUZXYTTE#*LMZ12003*EXT

## Sheet LMG342X_BB_EVM_Hardware.SchDoc
size 431 x 279 mm; Date: Not shown in title block; ApprovedBy: Not shown in title block; CheckedBy: Not shown in title block; Author: Not shown in title block; CompanyName: Not shown in title block; Engineer: Not shown in title block; Organization: Not shown in title block; Address1: Not shown in title block; Address2: Not shown in title block; Address3: Not shown in title block; Address4: Not shown in title block; DocumentNumber: 1; Revision: Use project parameter SCH_Rev; SheetNumber: 3; SheetTotal: 3; PageSetup: Record=PageOptions¦CenterHorizontal=True¦CenterVertical=True¦PrintScale=1.00¦XCorrection=1.00¦YCorrection=1.00¦PrintKind=0¦BorderSize=5000000¦LeftOffset=0¦BottomOffset=0¦Orientation=2¦PaperLength=1000¦PaperWidth=1000¦Scale=100¦PaperSource=15¦PrintQuality=600¦MediaType=1¦DitherType=10¦PaperKind=Letter¦PrintScaleMode=1
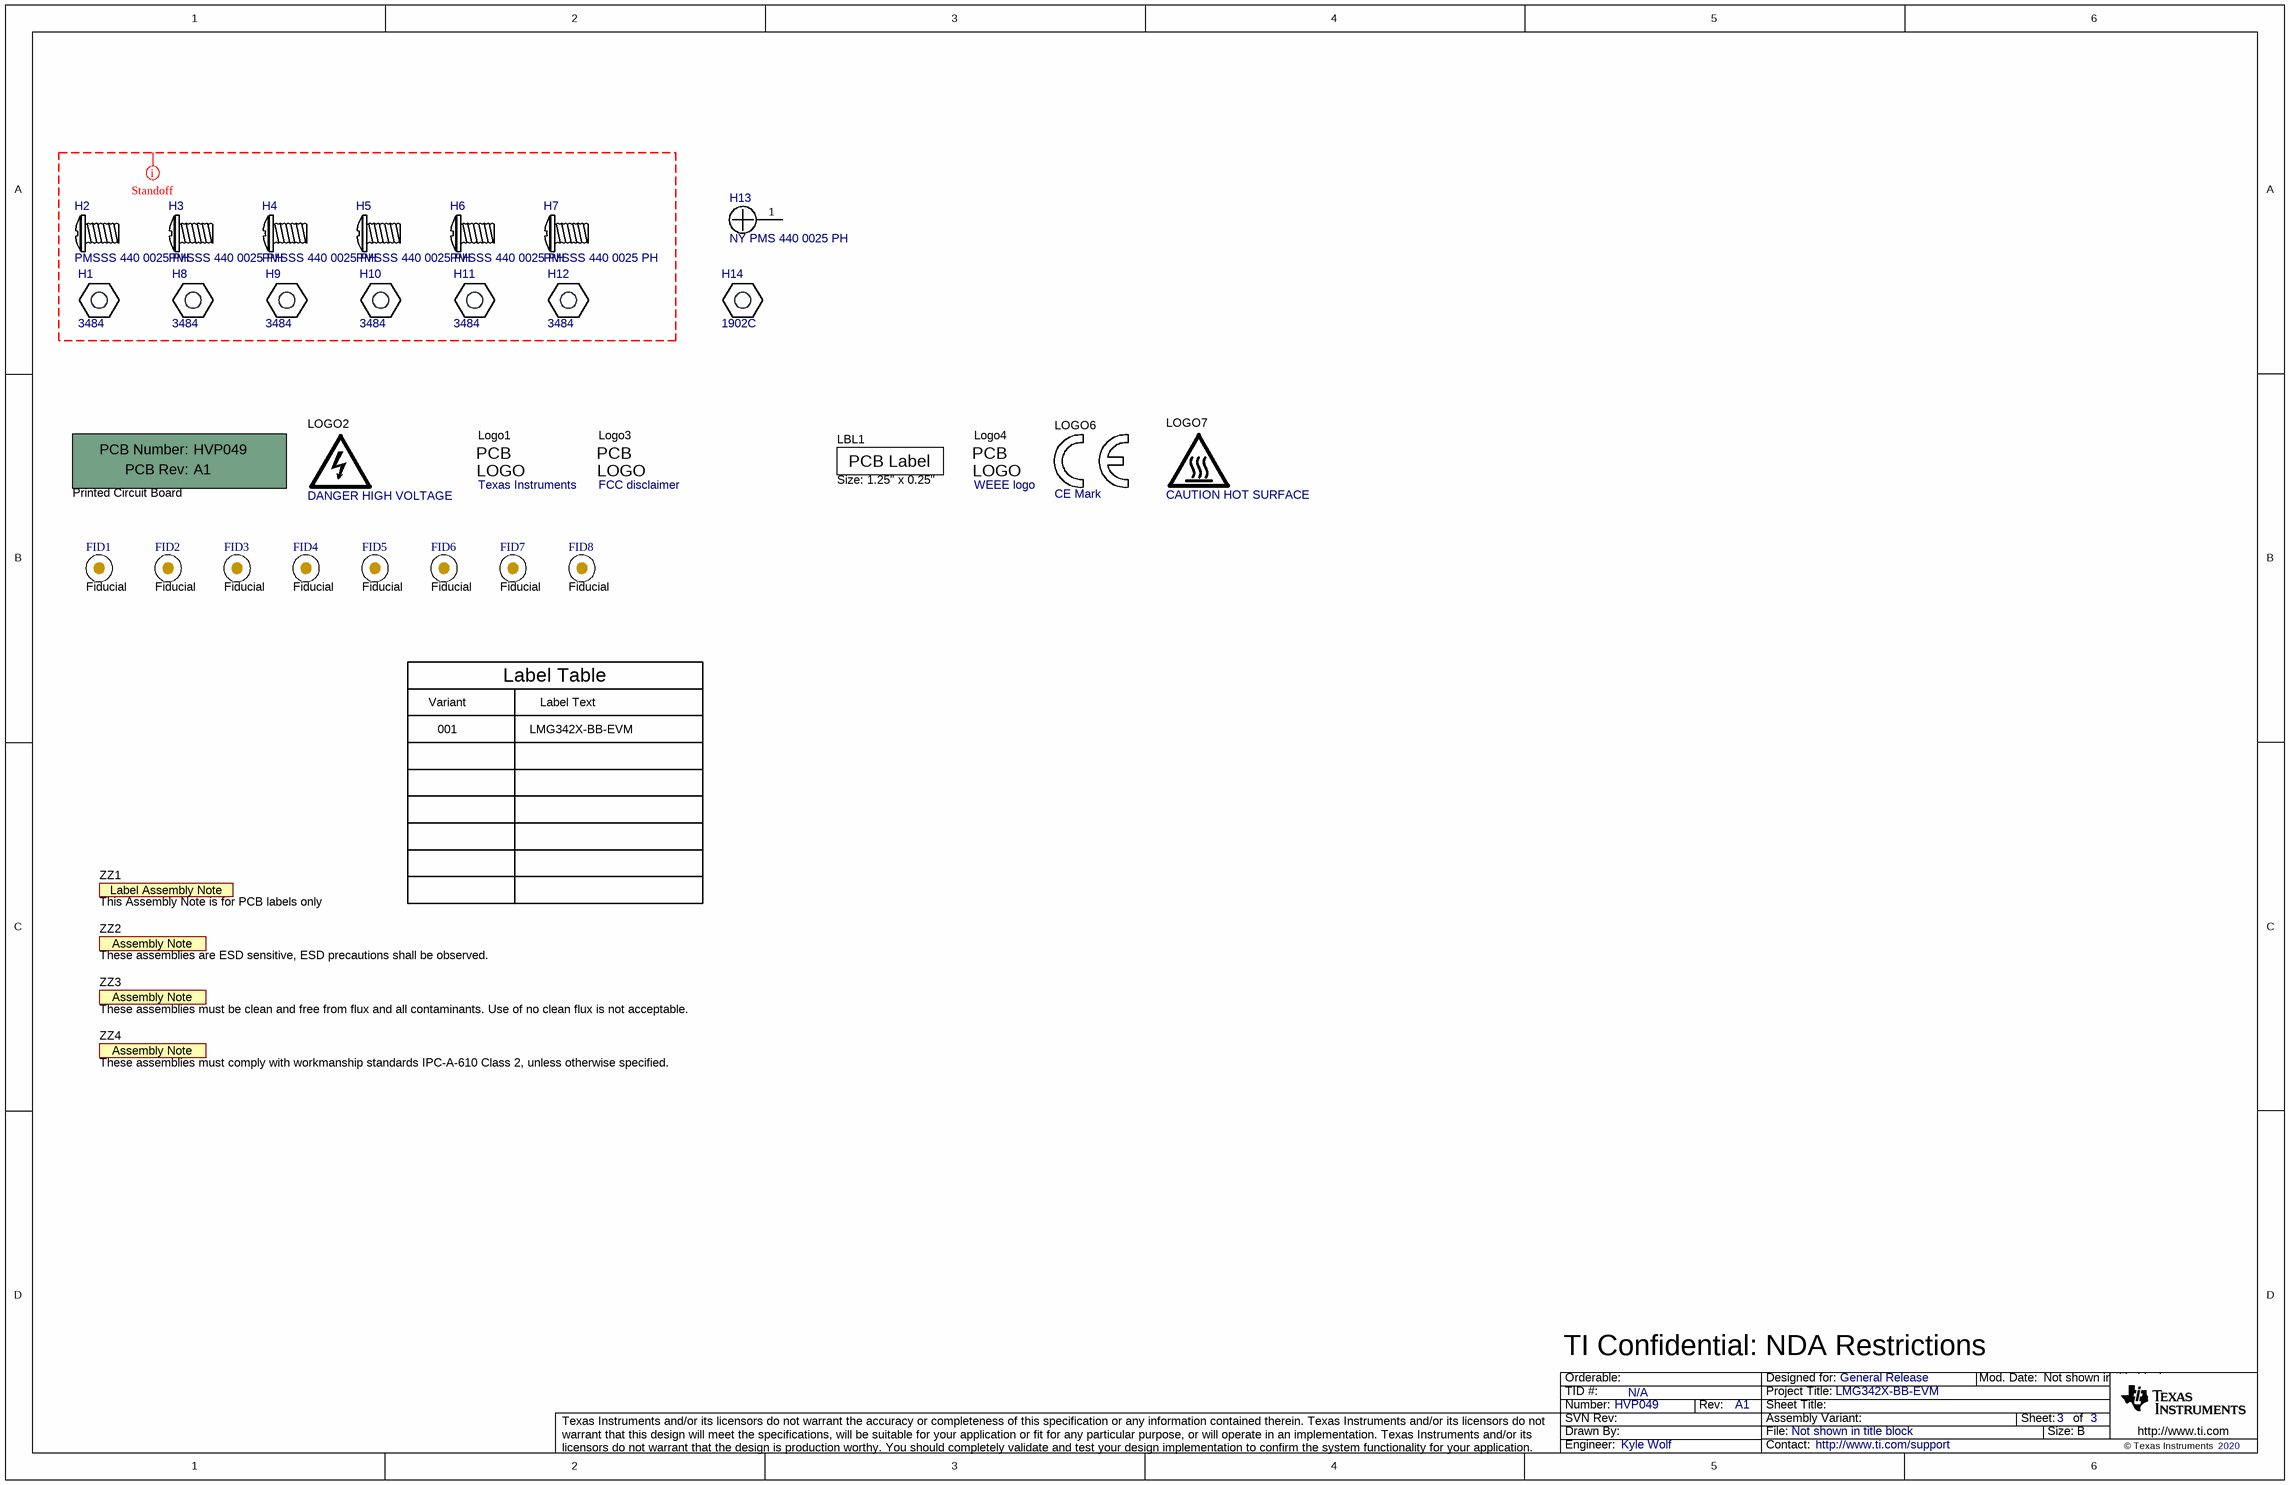
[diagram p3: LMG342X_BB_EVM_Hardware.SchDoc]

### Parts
!PCB  Printed Circuit Board  (mechanical)
FID1  Fiducial  [Fiducial10-20]
FID2  Fiducial  [Fiducial10-20]
FID3  Fiducial  [Fiducial10-20]
FID4  Fiducial  [Fiducial10-20]
FID5  Fiducial  [Fiducial10-20]
FID6  Fiducial  [Fiducial10-20]
FID7  Fiducial  [Fiducial10-20]
FID8  Fiducial  [Fiducial10-20]
H1  3484  [Keystone_3484]
H2  PMSSS 440 0025 PH  [B_F_PMSSS4400025PH]
H3  PMSSS 440 0025 PH  [B_F_PMSSS4400025PH]
H4  PMSSS 440 0025 PH  [B_F_PMSSS4400025PH]
H5  PMSSS 440 0025 PH  [B_F_PMSSS4400025PH]
H6  PMSSS 440 0025 PH  [B_F_PMSSS4400025PH]
H7  PMSSS 440 0025 PH  [B_F_PMSSS4400025PH]
H8  3484  [Keystone_3484]
H9  3484  [Keystone_3484]
H10  3484  [Keystone_3484]
H11  3484  [Keystone_3484]
H12  3484  [Keystone_3484]
H13  NY PMS 440 0025 PH  [NY PMS 440 0025 PH]
H14  1902C  [Keystone_1902C]
LBL1  Size: 1.25" x 0.25"  [Label_1250x250]
Logo1  Texas Instruments  [TI_Horizontal_Overlay_Medium]  (no BOM)
LOGO2  DANGER HIGH VOLTAGE  [IEC_HighVoltage_Large]  (no BOM)
Logo3  FCC disclaimer  [FCC_disclaimer]  (no BOM)
Logo4  WEEE logo  [WEEE_Minimum]  (no BOM)
LOGO6  CE Mark  [CE_Mark_5mm]  (no BOM)
LOGO7  CAUTION HOT SURFACE  [IEC_HotSurface_Large]  (no BOM)
ZZ1  This Assembly Note is for PCB labels only  [AssemblyNoteLabel]  (no BOM)
ZZ2  These assemblies are ESD sensitive, ESD precautions shall be observed.  [AssemblyNote]  (no BOM)
ZZ3  These assemblies must be clean and free from flux and all contaminants. Use of no clean flux is not acceptable.  [AssemblyNote]  (no BOM)
ZZ4  These assemblies must comply with workmanship standards IPC-A-610 Class 2, unless otherwise specified.  [AssemblyNote]  (no BOM)

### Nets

Not connected (* = marked no-connect by the designer): H13 1

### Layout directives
net class SigHeader: (no net found under the mark)

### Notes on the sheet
- Variant
- Label Table
- Label Text
- 001
- LMG342X-BB-EVM
- TI Confidential: NDA Restrictions

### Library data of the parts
!PCB = CMP-0003618-2: PartNumber: HVP049; Manufacturer: Any
FID1-FID8 = CMP-0077181-1: Fiducial mark.  There is nothing to buy or mount.
H1 H8-H12 = CMP-0003994-1: Manufacturer: Keystone; CompType: Standoff
H2-H7 = CMP-0003715-1: MACHINE SCREW PAN PHILLIPS 4-40; Manufacturer: B&F Fastener Supply; CompType: Standoff
H13 = CMP-0003617-1: Machine Screw, Round, #4-40 x 1/4, Nylon, Philips panhead; Manufacturer: B&F Fastener Supply; CompType: Hardware
H14 = CMP-0003610-1: Manufacturer: Keystone; CompType: Hardware
LBL1 = THT-13-457-10: Thermal Transfer Printable Labels, 1.250" W x 0.250" H - 10,000 per roll; Manufacturer: Brady; SymbolCreator: a0412235; CompType: Label
Logo1 = CMP-0074838-1: Texas Instrument Corporate Signature; SymbolCreator: a0412235; Lib Reference: TI_Logo
LOGO2 = CMP-0074835-1: IEC 61010-1 High Voltage Warning; SymbolCreator: a0412235
Logo3 = CMP-0074847-1: FCC_disclaimer
Logo4 = CMP-0074769-1
LOGO6 = CMP-0074844-1: SymbolCreator: a0412235
LOGO7 = CMP-0074837-1: IEC 61010-1 Hot Surface Warning; SymbolCreator: a0412235
ZZ1 = AssemblyNoteLabel: SymbolCreator: a0412235
ZZ2-ZZ4 = AssemblyNote: SymbolCreator: codlsc

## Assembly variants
001: not fitted C10 C12 FID1 FID2 FID3 SW1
